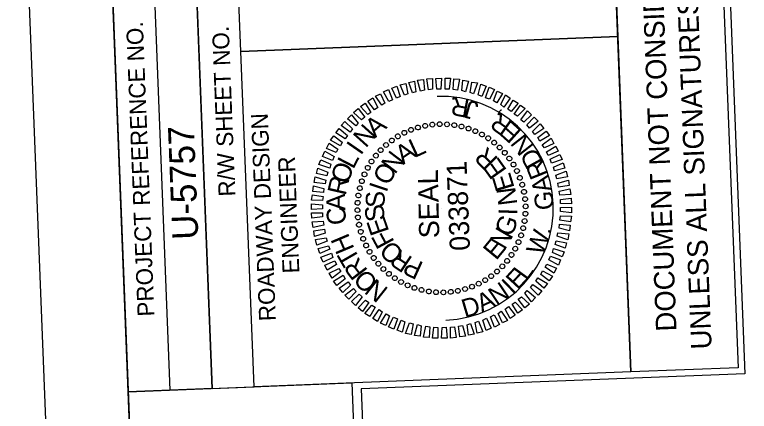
# Model space of a CAD drawing. Extents: x 1627855 to 1629021, y 762567 to 764488.
# Drawn here: x 1627855.1 to 1628074.2, y 764036.3 to 764154.6 of the extents above; entities that cross this region are included whole.
import ezdxf

# ---------------------------------------------------------------- set-up
doc = ezdxf.new("R2010")
doc.units = 0
for name, color, linetype in [('Old_Level_58', 7, 'Continuous'), ('Scratch_Level_0', 7, 'Continuous'), ('Sheet Clip Boundary CELL', 7, 'Continuous'), ('Sheet Data Field CELL', 7, 'Continuous'), ('Sheet Plan And Profile CELL', 7, 'Continuous'), ('Sheet Plot Border Outside CELL', 7, 'Continuous'), ('Sheet Professional Seal CELL', 7, 'Continuous'), ('Sheet Profile Grid Minor CELL', 7, 'Continuous'), ('Sheet Sticker Exception Certification CELL', 7, 'Continuous')]:
    doc.layers.add(name, color=color, linetype=linetype)

msp = doc.modelspace()

# ---------------------------------------------------------------- linework, layer by layer
at = {"layer": 'Old_Level_58'}
msp.add_lwpolyline([(1627896.85, 763842.26), (1627888.97, 764042.15), (1627955.61, 764044.78), (1627963.49, 763844.89)], close=True, dxfattribs=at)
at = {"layer": 'Scratch_Level_0'}
msp.add_arc((1627982.4, 764096.87), 33.36, 272.2582, 92.2582, dxfattribs=at)
at = {"layer": 'Sheet Clip Boundary CELL'}
msp.add_lwpolyline([(1628522.47, 764228.52), (1628282.65, 764219.07), (1628066.45, 764210.34), (1628072.87, 764047.54), (1627958.4, 764043.02), (1627966.27, 763843.29), (1627900.75, 763840.71), (1627941.6, 762804.67), (1628337.82, 762820.15), (1628577.63, 762829.61), (1628634.82, 762831.83), (1628637.13, 762773.12), (1628655.42, 762773.84), (1628653.1, 762832.57), (1628984.86, 762845.59), (1628929.69, 764244.53)], close=True, dxfattribs=at)
at = {"layer": 'Sheet Plan And Profile CELL'}
for p, q in [((1627914, 764043.14), (1627906.12, 764243.04)), ((1627901.51, 764042.65), (1627893.63, 764242.54)), ((1627922.55, 764143.61), (1628034.91, 764148.04)), ((1627914, 764043.14), (1627926.49, 764043.63))]:
    msp.add_line(p, q, dxfattribs=at)
for points in [[(1627881.09, 764242.05), (1627940.19, 762743.21), (1628989.38, 762784.59), (1628930.27, 764283.42)], [(1627922.55, 764143.61), (1627918.61, 764243.53), (1628031.02, 764247.96), (1628034.96, 764148.04)], [(1627888.97, 764042.15), (1627881.09, 764242.05), (1627906.12, 764243.04), (1627914, 764043.14)], [(1627926.49, 764043.63), (1627922.55, 764143.61), (1628034.96, 764148.04), (1628038.9, 764048.07)]]:
    msp.add_lwpolyline(points, close=True, dxfattribs=at)
at = {"layer": 'Sheet Plot Border Outside CELL'}
msp.add_lwpolyline([(1629021.25, 762610.71), (1628954.27, 764309.39), (1627855.12, 764266.04), (1627922.11, 762567.36)], close=True, dxfattribs=at)
at = {"layer": 'Sheet Professional Seal CELL'}
for p, q in [((1627973.27, 764120.28), (1627973.27, 764120.28)), ((1627975.35, 764120.96), (1627975.35, 764120.96)), ((1627977.53, 764121.45), (1627977.53, 764121.45)), ((1627979.67, 764121.83), (1627979.67, 764121.83)), ((1627981.86, 764121.97), (1627981.86, 764121.97)), ((1627984.07, 764121.9), (1627984.07, 764121.9)), ((1627986.23, 764121.64), (1627986.23, 764121.64)), ((1627988.34, 764121.27), (1627988.34, 764121.27)), ((1627990.47, 764120.65), (1627990.47, 764120.65)), ((1627969.4, 764118.32), (1627969.4, 764118.32)), ((1627971.31, 764119.4), (1627971.31, 764119.4)), ((1627992.5, 764119.83), (1627992.5, 764119.83)), ((1627994.49, 764118.91), (1627994.49, 764118.91)), ((1627967.54, 764117.1), (1627967.54, 764117.1)), ((1627996.34, 764117.73), (1627996.34, 764117.73)), ((1627998.14, 764116.45), (1627998.14, 764116.45)), ((1627964.25, 764114.22), (1627964.25, 764114.22)), ((1627965.84, 764115.78), (1627965.84, 764115.78)), ((1627999.75, 764115.02), (1627999.75, 764115.02)), ((1627962.82, 764112.61), (1627962.82, 764112.61)), ((1628001.31, 764113.43), (1628001.31, 764113.43)), ((1628002.63, 764111.73), (1628002.63, 764111.73)), ((1627961.54, 764110.81), (1627961.54, 764110.81)), ((1628003.86, 764109.87), (1628003.86, 764109.87)), ((1627960.36, 764108.96), (1627960.36, 764108.96)), ((1628004.93, 764107.96), (1628004.93, 764107.96)), ((1627958.62, 764104.94), (1627958.62, 764104.94)), ((1627959.44, 764106.97), (1627959.44, 764106.97)), ((1628005.81, 764106), (1628005.81, 764106)), ((1627958, 764102.81), (1627958, 764102.81)), ((1628006.49, 764103.92), (1628006.49, 764103.92)), ((1627957.63, 764100.7), (1627957.63, 764100.7)), ((1628006.98, 764101.74), (1628006.98, 764101.74)), ((1627957.37, 764098.53), (1627957.37, 764098.53)), ((1628007.36, 764099.6), (1628007.36, 764099.6)), ((1627957.3, 764096.33), (1627957.3, 764096.33)), ((1627982.4, 764096.87), (1627982.4, 764096.87)), ((1628007.5, 764097.41), (1628007.5, 764097.41)), ((1627957.44, 764094.13), (1627957.44, 764094.13)), ((1628007.44, 764095.2), (1628007.44, 764095.2)), ((1627957.82, 764092), (1627957.82, 764092)), ((1628007.17, 764093.04), (1628007.17, 764093.04)), ((1627958.31, 764089.81), (1627958.31, 764089.81)), ((1628006.8, 764090.93), (1628006.8, 764090.93)), ((1627958.99, 764087.74), (1627958.99, 764087.74)), ((1628006.19, 764088.8), (1628006.19, 764088.8)), ((1627959.87, 764085.77), (1627959.87, 764085.77)), ((1628005.37, 764086.77), (1628005.37, 764086.77)), ((1627960.95, 764083.86), (1627960.95, 764083.86)), ((1628003.27, 764082.93), (1628003.27, 764082.93)), ((1628004.45, 764084.78), (1628004.45, 764084.78)), ((1627962.17, 764082.01), (1627962.17, 764082.01)), ((1628001.99, 764081.13), (1628001.99, 764081.13)), ((1627963.49, 764080.31), (1627963.49, 764080.31)), ((1627965.05, 764078.72), (1627965.05, 764078.72)), ((1628000.55, 764079.52), (1628000.55, 764079.52)), ((1627966.66, 764077.28), (1627966.66, 764077.28)), ((1627997.26, 764076.64), (1627997.26, 764076.64)), ((1627998.96, 764077.96), (1627998.96, 764077.96)), ((1627968.46, 764076), (1627968.46, 764076)), ((1627970.31, 764074.82), (1627970.31, 764074.82)), ((1627993.5, 764074.34), (1627993.5, 764074.34)), ((1627995.41, 764075.41), (1627995.41, 764075.41)), ((1627972.3, 764073.9), (1627972.3, 764073.9)), ((1627974.33, 764073.08), (1627974.33, 764073.08)), ((1627976.46, 764072.47), (1627976.46, 764072.47)), ((1627978.57, 764072.1), (1627978.57, 764072.1)), ((1627987.27, 764072.29), (1627987.27, 764072.29)), ((1627989.46, 764072.78), (1627989.46, 764072.78)), ((1627991.53, 764073.46), (1627991.53, 764073.46)), ((1627980.74, 764071.83), (1627980.74, 764071.83)), ((1627982.94, 764071.77), (1627982.94, 764071.77)), ((1627985.14, 764071.91), (1627985.14, 764071.91))]:
    msp.add_line(p, q, dxfattribs=at)
for points in [[(1627978.51, 764132.19), (1627977.98, 764135.42), (1627979.67, 764135.59), (1627979.7, 764132.34)], [(1627981, 764132.34), (1627980.72, 764135.58), (1627982.42, 764135.65), (1627982.2, 764132.39)], [(1627983.5, 764132.39), (1627983.47, 764135.64), (1627985.13, 764135.61), (1627984.71, 764132.34)], [(1627971.37, 764130.56), (1627970.09, 764133.71), (1627971.73, 764134.08), (1627972.4, 764130.95)], [(1627973.74, 764131.25), (1627972.67, 764134.36), (1627974.35, 764134.73), (1627974.78, 764131.59)], [(1627976.12, 764131.8), (1627975.29, 764135.02), (1627976.99, 764135.23), (1627977.31, 764132.05)], [(1627985.91, 764132.23), (1627986.08, 764135.44), (1627987.79, 764135.31), (1627987.12, 764132.03)], [(1627988.47, 764131.93), (1627988.75, 764135.05), (1627990.46, 764134.77), (1627989.54, 764131.58)], [(1627990.9, 764131.38), (1627991.43, 764134.5), (1627993.09, 764134.22), (1627991.96, 764131.02)], [(1627993.33, 764130.72), (1627994.1, 764133.86), (1627995.68, 764133.27), (1627994.4, 764130.22)], [(1627966.69, 764128.67), (1627965.07, 764131.56), (1627966.64, 764132.27), (1627967.77, 764129.22)], [(1627969, 764129.67), (1627967.58, 764132.66), (1627969.11, 764133.27), (1627970.03, 764130.21)], [(1627995.56, 764129.81), (1627996.59, 764132.96), (1627998.17, 764132.27), (1627996.68, 764129.36)], [(1627997.9, 764128.9), (1627999.04, 764131.8), (1628000.62, 764131.11), (1627998.87, 764128.34)], [(1627962.43, 764126.2), (1627960.43, 764128.78), (1627961.89, 764129.79), (1627963.4, 764126.94)], [(1627964.58, 764127.59), (1627962.72, 764130.32), (1627964.24, 764131.03), (1627965.5, 764128.23)], [(1628000.1, 764127.79), (1628001.49, 764130.65), (1628002.92, 764129.7), (1628001.03, 764127.03)], [(1628002.15, 764126.37), (1628003.75, 764129.13), (1628005.23, 764128.24), (1628003.13, 764125.76)], [(1627960.43, 764124.82), (1627958.24, 764127.19), (1627959.65, 764128.2), (1627961.36, 764125.46)], [(1628004.11, 764124.95), (1628005.96, 764127.62), (1628007.3, 764126.57), (1628005.04, 764124.28)], [(1627956.81, 764121.43), (1627954.38, 764123.48), (1627955.53, 764124.73), (1627957.58, 764122.21)], [(1627958.54, 764123.25), (1627956.2, 764125.46), (1627957.51, 764126.56), (1627959.52, 764123.99)], [(1628006.08, 764123.27), (1628008.03, 764125.9), (1628009.23, 764124.7), (1628006.91, 764122.5)], [(1627955.14, 764119.56), (1627952.46, 764121.51), (1627953.61, 764122.75), (1627955.85, 764120.54)], [(1628007.89, 764121.69), (1628010, 764123.98), (1628011.25, 764122.83), (1628008.63, 764120.77)], [(1627953.66, 764117.6), (1627950.84, 764119.34), (1627951.89, 764120.68), (1627954.32, 764118.58)], [(1628009.52, 764119.75), (1628011.83, 764122), (1628012.94, 764120.69), (1628010.21, 764118.83)], [(1627952.24, 764115.49), (1627949.28, 764117.13), (1627950.28, 764118.47), (1627952.8, 764116.62)], [(1628011.09, 764117.92), (1628013.57, 764119.86), (1628014.57, 764118.6), (1628011.74, 764116.84)], [(1627950.97, 764113.49), (1627948.07, 764114.73), (1627948.86, 764116.26), (1627951.53, 764114.47)], [(1628012.43, 764115.77), (1628015.06, 764117.72), (1628015.92, 764116.2), (1628013.07, 764114.84)], [(1627949.91, 764111.15), (1627946.92, 764112.28), (1627947.56, 764113.86), (1627950.42, 764112.27)], [(1628013.71, 764113.67), (1628016.45, 764115.37), (1628017.21, 764113.85), (1628014.21, 764112.58)], [(1628014.85, 764111.51), (1628017.7, 764112.92), (1628018.36, 764111.45), (1628015.2, 764110.27)], [(1627949.05, 764108.86), (1627945.86, 764109.89), (1627946.4, 764111.31), (1627949.36, 764110.03)], [(1628015.75, 764109.09), (1628018.7, 764110.36), (1628019.21, 764108.83), (1628016.14, 764108.06)], [(1627948.24, 764106.58), (1627945.12, 764107.21), (1627945.55, 764108.78), (1627948.55, 764107.64)], [(1628016.49, 764106.72), (1628019.6, 764107.89), (1628020.01, 764106.21), (1628016.78, 764105.68)], [(1627947.69, 764104.16), (1627944.42, 764104.53), (1627944.75, 764106.24), (1627947.9, 764105.22)], [(1628017.13, 764104.34), (1628020.3, 764105.27), (1628020.51, 764103.63), (1628017.33, 764103.15)], [(1627947.24, 764101.59), (1627944.02, 764101.91), (1627944.21, 764103.57), (1627947.34, 764102.79)], [(1627946.93, 764099.17), (1627943.68, 764099.24), (1627943.91, 764100.9), (1627947.09, 764100.38)], [(1628017.53, 764101.96), (1628020.7, 764102.63), (1628020.97, 764100.94), (1628017.73, 764100.76)], [(1628017.88, 764099.47), (1628021.11, 764099.85), (1628021.13, 764098.2), (1628017.87, 764098.27)], [(1627946.88, 764096.67), (1627943.63, 764096.54), (1627943.62, 764098.19), (1627946.88, 764097.87)], [(1628017.92, 764097.07), (1628021.17, 764097.2), (1628021.18, 764095.55), (1628017.92, 764095.87)], [(1627946.93, 764094.27), (1627943.69, 764093.89), (1627943.67, 764095.54), (1627946.93, 764095.47)], [(1628017.87, 764094.56), (1628021.13, 764094.49), (1628020.89, 764092.83), (1628017.72, 764093.36)], [(1627947.27, 764091.78), (1627944.1, 764091.1), (1627943.83, 764092.8), (1627947.08, 764092.97)], [(1628017.56, 764092.15), (1628020.78, 764091.83), (1628020.6, 764090.17), (1628017.46, 764090.95)], [(1627947.67, 764089.39), (1627944.5, 764088.47), (1627944.29, 764090.11), (1627947.47, 764090.59)], [(1628017.12, 764089.58), (1628020.38, 764089.21), (1628020.05, 764087.49), (1628016.91, 764088.52)], [(1627948.31, 764087.02), (1627945.21, 764085.84), (1627944.79, 764087.53), (1627948.02, 764088.06)], [(1627949.06, 764084.64), (1627946.1, 764083.38), (1627945.59, 764084.91), (1627948.67, 764085.68)], [(1628016.56, 764087.16), (1628019.69, 764086.53), (1628019.25, 764084.96), (1628016.25, 764086.09)], [(1627949.95, 764082.23), (1627947.11, 764080.82), (1627946.45, 764082.29), (1627949.6, 764083.47)], [(1628015.75, 764084.87), (1628018.94, 764083.85), (1628018.4, 764082.43), (1628015.45, 764083.71)], [(1627951.09, 764080.07), (1627948.35, 764078.36), (1627947.59, 764079.88), (1627950.6, 764081.15)], [(1628014.89, 764082.59), (1628017.89, 764081.45), (1628017.25, 764079.88), (1628014.38, 764081.47)], [(1627952.37, 764077.97), (1627949.75, 764076.02), (1627948.89, 764077.53), (1627951.74, 764078.9)], [(1628013.83, 764080.24), (1628016.73, 764079.01), (1628015.94, 764077.47), (1628013.27, 764079.27)], [(1627953.71, 764075.82), (1627951.23, 764073.87), (1627950.23, 764075.13), (1627953.07, 764076.9)], [(1628012.56, 764078.24), (1628015.53, 764076.61), (1628014.53, 764075.27), (1628012, 764077.12)], [(1627955.28, 764073.98), (1627952.97, 764071.74), (1627951.87, 764073.05), (1627954.6, 764074.91)], [(1628009.67, 764074.17), (1628012.35, 764072.23), (1628011.19, 764070.98), (1628008.95, 764073.2)], [(1628011.14, 764076.13), (1628013.96, 764074.39), (1628012.91, 764073.05), (1628010.48, 764075.16)], [(1627956.91, 764072.04), (1627954.8, 764069.76), (1627953.55, 764070.91), (1627956.17, 764072.97)], [(1628007.99, 764072.31), (1628010.42, 764070.25), (1628009.27, 764069.01), (1628007.22, 764071.53)], [(1627958.72, 764070.46), (1627956.78, 764067.84), (1627955.58, 764069.04), (1627957.89, 764071.23)], [(1628006.26, 764070.49), (1628008.6, 764068.28), (1628007.29, 764067.18), (1628005.29, 764069.75)], [(1627960.69, 764068.79), (1627958.85, 764066.12), (1627957.5, 764067.16), (1627959.76, 764069.45)], [(1627962.65, 764067.37), (1627961.06, 764064.6), (1627959.57, 764065.49), (1627961.67, 764067.98)], [(1628004.37, 764068.91), (1628006.57, 764066.55), (1628005.15, 764065.54), (1628003.44, 764068.28)], [(1627964.71, 764065.95), (1627963.32, 764063.09), (1627961.88, 764064.03), (1627963.78, 764066.71)], [(1628000.23, 764066.15), (1628002.08, 764063.42), (1628000.56, 764062.71), (1627999.3, 764065.51)], [(1628002.37, 764067.53), (1628004.38, 764064.96), (1628002.91, 764063.95), (1628001.4, 764066.79)], [(1627966.9, 764064.83), (1627965.77, 764061.94), (1627964.19, 764062.62), (1627965.93, 764065.39)], [(1627969.24, 764063.92), (1627968.21, 764060.78), (1627966.63, 764061.47), (1627968.12, 764064.38)], [(1627971.48, 764063.01), (1627970.7, 764059.88), (1627969.13, 764060.47), (1627970.41, 764063.52)], [(1627995.8, 764064.07), (1627997.22, 764061.07), (1627995.7, 764060.46), (1627994.77, 764063.53)], [(1627998.12, 764065.06), (1627999.73, 764062.17), (1627998.16, 764061.46), (1627997.04, 764064.52)], [(1627973.9, 764062.36), (1627973.38, 764059.23), (1627971.71, 764059.52), (1627972.84, 764062.71)], [(1627976.33, 764061.8), (1627976.05, 764058.69), (1627974.34, 764058.97), (1627975.26, 764062.16)], [(1627978.89, 764061.5), (1627978.72, 764058.29), (1627977.01, 764058.43), (1627977.68, 764061.71)], [(1627981.3, 764061.35), (1627981.33, 764058.1), (1627979.68, 764058.13), (1627980.1, 764061.4)], [(1627983.8, 764061.4), (1627984.08, 764058.15), (1627982.38, 764058.09), (1627982.6, 764061.35)], [(1627986.3, 764061.54), (1627986.82, 764058.31), (1627985.13, 764058.15), (1627985.1, 764061.4)], [(1627988.68, 764061.94), (1627989.51, 764058.72), (1627987.82, 764058.5), (1627987.49, 764061.69)], [(1627991.06, 764062.48), (1627992.14, 764059.37), (1627990.45, 764059.01), (1627990.03, 764062.14)], [(1627993.44, 764063.18), (1627994.71, 764060.02), (1627993.08, 764059.66), (1627992.4, 764062.79)]]:
    msp.add_lwpolyline(points, close=True, dxfattribs=at)
for centre, major_axis in [((1627979.67, 764121.8), (-0.078, 0.716)), ((1627981.85, 764121.94), (-0.016, 0.72)), ((1627984.04, 764121.89), (0.047, 0.718)), ((1627986.21, 764121.66), (0.109, 0.712)), ((1627971.31, 764119.36), (-0.319, 0.646)), ((1627973.31, 764120.24), (-0.261, 0.671)), ((1627975.38, 764120.95), (-0.202, 0.691)), ((1627977.51, 764121.47), (-0.141, 0.706)), ((1627988.36, 764121.23), (0.171, 0.699)), ((1627990.46, 764120.62), (0.231, 0.682)), ((1627992.5, 764119.83), (0.29, 0.659)), ((1627969.39, 764118.31), (-0.374, 0.615)), ((1627994.46, 764118.86), (0.346, 0.631)), ((1627996.33, 764117.72), (0.4, 0.599)), ((1627965.86, 764115.72), (-0.475, 0.541)), ((1627967.57, 764117.09), (-0.426, 0.581)), ((1627998.1, 764116.43), (0.451, 0.562)), ((1627964.28, 764114.21), (-0.52, 0.498)), ((1627999.74, 764114.99), (0.498, 0.52)), ((1628001.26, 764113.41), (0.541, 0.475)), ((1627961.55, 764110.8), (-0.599, 0.4)), ((1627962.84, 764112.56), (-0.562, 0.451)), ((1628002.63, 764111.7), (0.581, 0.426)), ((1627960.41, 764108.93), (-0.631, 0.346)), ((1628003.84, 764109.88), (0.615, 0.374)), ((1627959.44, 764106.97), (-0.659, 0.29)), ((1628004.89, 764107.96), (0.646, 0.319)), ((1627958.65, 764104.93), (-0.682, 0.231)), ((1628005.78, 764105.96), (0.671, 0.261)), ((1627958.04, 764102.83), (-0.699, 0.171)), ((1628006.48, 764103.89), (0.691, 0.202)), ((1627957.61, 764100.68), (-0.712, 0.109)), ((1628007, 764101.76), (0.706, 0.141)), ((1627957.38, 764098.5), (-0.718, 0.047)), ((1628007.33, 764099.6), (0.716, 0.078)), ((1627957.33, 764096.32), (-0.72, -0.016)), ((1628007.48, 764097.42), (0.72, 0.016)), ((1627957.47, 764094.13), (-0.716, -0.078)), ((1628007.43, 764095.23), (0.718, -0.047)), ((1627957.8, 764091.97), (-0.706, -0.141)), ((1628006.76, 764090.91), (0.699, -0.171)), ((1628007.19, 764093.06), (0.712, -0.109)), ((1627958.32, 764089.85), (-0.691, -0.202)), ((1628006.15, 764088.81), (0.682, -0.231)), ((1627959.03, 764087.77), (-0.671, -0.261)), ((1628005.36, 764086.77), (0.659, -0.29)), ((1627959.91, 764085.77), (-0.646, -0.319)), ((1628004.39, 764084.81), (0.631, -0.346)), ((1627960.96, 764083.85), (-0.615, -0.374)), ((1628003.26, 764082.94), (0.599, -0.4)), ((1627962.18, 764082.04), (-0.581, -0.426)), ((1627963.55, 764080.33), (-0.541, -0.475)), ((1628001.96, 764081.17), (0.562, -0.451)), ((1627965.06, 764078.75), (-0.498, -0.52)), ((1627998.94, 764078.01), (0.475, -0.541)), ((1628000.52, 764079.53), (0.52, -0.498)), ((1627966.71, 764077.31), (-0.451, -0.562)), ((1627968.47, 764076.01), (-0.4, -0.599)), ((1627997.23, 764076.64), (0.426, -0.581)), ((1627970.34, 764074.88), (-0.346, -0.631)), ((1627972.3, 764073.91), (-0.29, -0.659)), ((1627991.49, 764073.49), (0.261, -0.671)), ((1627993.5, 764074.38), (0.319, -0.646)), ((1627995.42, 764075.43), (0.374, -0.615)), ((1627974.34, 764073.12), (-0.231, -0.682)), ((1627976.44, 764072.51), (-0.171, -0.699)), ((1627978.59, 764072.08), (-0.109, -0.712)), ((1627980.76, 764071.84), (-0.047, -0.718)), ((1627982.95, 764071.79), (0.016, -0.72)), ((1627985.14, 764071.94), (0.078, -0.716)), ((1627987.3, 764072.27), (0.141, -0.706)), ((1627989.42, 764072.79), (0.202, -0.691))]:
    msp.add_ellipse(centre, major_axis=major_axis, ratio=0.999708, dxfattribs=at)
at = {"layer": 'Sheet Sticker Exception Certification CELL'}
for p, q in [((1628038.89, 764048.07), (1628031.01, 764247.96)), ((1628062.96, 764249.22), (1628070.84, 764049.33)), ((1628070.84, 764049.33), (1628038.89, 764048.07))]:
    msp.add_line(p, q, dxfattribs=at)

# ---------------------------------------------------------------- texts
at = {"layer": 'Sheet Data Field CELL'}
msp.add_text('U-5757', height=7.75, rotation=92.2582, dxfattribs=at).set_placement((1627909.9, 764087.63))
at = {"layer": 'Sheet Plan And Profile CELL'}
for s, height, p in [('PROJECT REFERENCE NO.', 5.0001, (1627896.79, 764064.68)), ('R/W SHEET NO.', 5.0001, (1627920.95, 764100.46)), ('ROADWAY DESIGN', 5.0001, (1627933.02, 764063.31)), ('ENGINEER', 5, (1627940.02, 764077.54))]:
    msp.add_text(s, height=height, rotation=92.2582, dxfattribs=at).set_placement(p)
at = {"layer": 'Sheet Professional Seal CELL'}
for s, height, rotation, p in [('A', 5.64, 40.8753, (1627962.62, 764117.7)), ('N', 5.64, 48.0771, (1627959.78, 764114.64)), ('I', 5.64, 55.2783, (1627958.32, 764112.43)), ('A', 5.64, 34.0185, (1627970.99, 764109.73)), ('L', 5.64, 24.659, (1627974.36, 764111.81)), ('N', 5.64, 52.7348, (1627968.5, 764106.78)), ('R', 5.64, 134.7396, (1627999.58, 764111.66)), ('L', 5.64, 62.4791, (1627956.08, 764108.29)), ('E', 5.64, 125.3823, (1628002.07, 764108.2)), ('O', 5.64, 69.6794, (1627954.41, 764103.82)), ('O', 5.64, 62.0917, (1627966.63, 764103.35)), ('SEAL', 5.998, 91.2582, (1627981.75, 764087.99)), ('E', 5.64, 106.67, (1628004.23, 764102.98)), ('R', 5.64, 76.8793, (1627953.79, 764100.44)), ('I', 5.64, 71.4478, (1627966.01, 764101.33)), ('N', 5.64, 97.3146, (1628005.02, 764098.06)), ('A', 5.64, 91.2785, (1627953.75, 764096.24)), ('S', 5.64, 90.1586, (1627965.48, 764097)), ('C', 5.64, 98.4781, (1627954.21, 764092.3)), ('S', 5.64, 99.5138, (1627965.68, 764093.41)), ('I', 5.64, 87.9594, (1628005, 764094.71)), ('E', 5.64, 108.8693, (1627966.86, 764090)), ('G', 5.64, 69.2484, (1628003.36, 764088.09)), ('N', 5.64, 59.8921, (1628001.27, 764084.2)), ('H', 5.64, 112.8777, (1627956.51, 764084.79)), ('F', 5.64, 118.2252, (1627968.49, 764086.86)), ('E', 5.64, 50.5351, (1627998.69, 764081.1)), ('O', 5.64, 136.9394, (1627971.56, 764083.68)), ('T', 5.64, 120.078, (1627958.28, 764081.61)), ('R', 5.64, 146.2978, (1627974.08, 764082.03)), ('R', 5.64, 127.2787, (1627960.62, 764078.3)), ('P', 5.64, 155.6571, (1627977.34, 764080.56)), ('O', 5.64, 134.4799, (1627963.85, 764074.97)), ('N', 5.64, 141.6817, (1627966.84, 764072.79))]:
    msp.add_text(s, height=height, rotation=rotation, dxfattribs=at).set_placement(p)
at = {"layer": 'Sheet Profile Grid Minor CELL'}
for s, height, rotation, p in [('R', 5.5, 169.6122, (1627991.04, 764129.21)), ('.', 5.5, 176.5387, (1627987.07, 764130.01)), ('J', 5.5, 164.7437, (1627993.75, 764128.36)), ('R', 5.5, 144.637, (1628003.88, 764122.54)), (',', 5.5, 151.5634, (1628000.63, 764124.94)), ('E', 5.5, 138.054, (1628006.68, 764119.9)), ('N', 5.5, 128.1223, (1628010.29, 764115.37)), ('D', 5.5, 118.9777, (1628012.88, 764110.7)), ('R', 5.5, 112.0512, (1628014.32, 764106.93)), ('033871', 5.998, 92.2582, (1627990.91, 764084.3)), ('A', 5.5, 103.8654, (1628015.43, 764102.28)), ('G', 5.5, 93.9337, (1628015.87, 764096.5)), ('W', 5.5, 69.1473, (1628012.63, 764082.5)), ('.', 5.5, 80.7534, (1628014.9, 764088.88)), ('E', 5.5, 47.309, (1628005.12, 764072.29)), ('L', 5.5, 53.892, (1628007.79, 764075.06)), ('N', 5.5, 33.8568, (1627998.78, 764067.68)), ('I', 5.5, 43.7885, (1628003.57, 764070.94)), ('D', 5.5, 16.5264, (1627989.34, 764064.13)), ('A', 5.5, 25.671, (1627994.46, 764065.64))]:
    msp.add_text(s, height=height, rotation=rotation, dxfattribs=at).set_placement(p)
at = {"layer": 'Sheet Sticker Exception Certification CELL'}
for s, p in [('UNLESS ALL SIGNATURES COMPLETED', (1628062.98, 764054.91)), ('DOCUMENT NOT CONSIDERED FINAL', (1628052.5, 764060.24))]:
    msp.add_text(s, height=6.124, rotation=92.2582, dxfattribs=at).set_placement(p)

doc.saveas('drawing.dxf')
